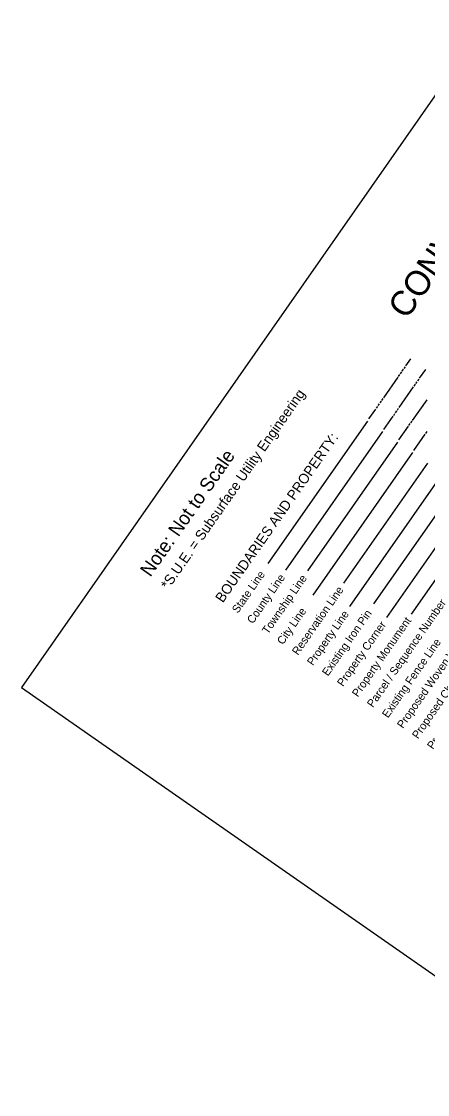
# Model space of a CAD drawing. Extents: x 1731327 to 1735374, y 884856 to 889832.
# Drawn here: x 1733509 to 1733952, y 888007 to 889180 of the extents above; entities that cross this region are included whole.
import ezdxf

# ---------------------------------------------------------------- set-up
doc = ezdxf.new("R2010")
doc.units = 0
doc.layers.add('Exist Utilities Telephone Pole CELL', color=7, linetype='Continuous')
doc.layers.add('Exist Vegetation Woods Line', color=7, linetype='Continuous')

msp = doc.modelspace()

# ---------------------------------------------------------------- linework, layer by layer
at = {"layer": 'Exist Utilities Telephone Pole CELL'}
msp.add_lwpolyline([(1734411, 887822.4), (1735374.4, 889203), (1734472.3, 889832.5), (1733508.9, 888451.9)], close=True, dxfattribs=at)
msp.add_lwpolyline([(1734411, 887822.4), (1735374.4, 889203), (1734472.3, 889832.5), (1733508.9, 888451.9)], close=True, dxfattribs=at)
at = {"layer": 'Exist Vegetation Woods Line'}
for p, q in [((1733928.8, 888803.2), (1733934.1, 888810.9)), ((1733924.8, 888797.5), (1733926.2, 888799.5)), ((1733926.8, 888800.4), (1733928.2, 888802.4)), ((1733943.7, 888789.7), (1733950.5, 888799.4)), ((1733904.5, 888768.4), (1733920.2, 888790.9)), ((1733920.8, 888791.8), (1733922.2, 888793.8)), ((1733922.8, 888794.6), (1733924.2, 888796.7)), ((1733941.7, 888786.8), (1733943.1, 888788.8)), ((1733921.4, 888757.7), (1733937.1, 888780.2)), ((1733937.7, 888781), (1733939.1, 888783.1)), ((1733939.7, 888783.9), (1733941.1, 888786)), ((1733900.5, 888762.7), (1733901.9, 888764.7)), ((1733902.5, 888765.5), (1733903.9, 888767.6)), ((1733936, 888743.7), (1733951.8, 888766.3)), ((1733888.3, 888745.3), (1733895.9, 888756.1)), ((1733896.5, 888756.9), (1733897.9, 888759)), ((1733898.5, 888759.8), (1733899.9, 888761.8)), ((1733917.4, 888751.9), (1733918.8, 888754)), ((1733919.4, 888754.8), (1733920.8, 888756.9)), ((1733886.7, 888742.9), (1733778, 888587.1)), ((1733904.7, 888733.8), (1733914.8, 888748.2)), ((1733915.4, 888749.1), (1733916.8, 888751.1)), ((1733934, 888740.9), (1733935.5, 888742.9)), ((1733903.1, 888731.5), (1733797.3, 888579.8)), ((1733921.1, 888722.4), (1733931.5, 888737.2)), ((1733932, 888738), (1733933.5, 888740.1)), ((1733937.5, 888710.9), (1733949.9, 888728.7)), ((1733950.5, 888729.5), (1733951.9, 888731.6)), ((1733919.5, 888720), (1733821.3, 888579.3)), ((1733935.9, 888708.6), (1733827.2, 888552.8)), ((1733952.3, 888697.1), (1733860.7, 888565.9)), ((1733968.7, 888685.7), (1733867.3, 888540.4)), ((1733985.1, 888674.3), (1733893.5, 888543)), ((1734001.5, 888662.8), (1733907.7, 888528.4)), ((1734017.9, 888651.4), (1733934.5, 888531.9))]:
    msp.add_line(p, q, dxfattribs=at)

# ---------------------------------------------------------------- texts
for s, height, p in [('CONVENTIONAL  PLAN SHEET SYMBOLS', 27.195, (1733929.6, 888853)), ('*S.U.E. = Subsurface Utility Engineering', 10.998, (1733669.3, 888558.1)), ('BOUNDARIES AND PROPERTY:', 10.998, (1733728.8, 888543.6)), ('Note: Not to Scale', 14.997, (1733649.7, 888571.7)), ('State Line', 8.75, (1733745.2, 888532.2)), ('County Line', 8.748, (1733761.6, 888520.7)), ('Township Line', 8.748, (1733778, 888509.3)), ('Reservation Line', 8.748, (1733810.8, 888486.4)), ('Parcel / Sequence Number', 8.748, (1733892.7, 888429.2)), ('City Line', 8.75, (1733794.4, 888497.8)), ('Property Line', 8.748, (1733827.2, 888475)), ('Existing Iron Pin', 8.748, (1733843.6, 888463.5)), ('Proposed Woven Wire Fence', 8.748, (1733925.5, 888406.3)), ('Property Corner', 8.748, (1733860, 888452.1)), ('Property Monument', 8.748, (1733876.3, 888440.6)), ('Proposed Chain Link Fence', 8.748, (1733941.9, 888394.9)), ('Proposed Barbed Wire Fence', 8.748, (1733958.3, 888383.4)), ('Existing Fence Line', 8.748, (1733909.1, 888417.7))]:
    msp.add_text(s, height=height, rotation=55.0911, dxfattribs=at).set_placement(p)

doc.saveas('drawing.dxf')
